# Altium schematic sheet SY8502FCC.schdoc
size 127 x 101 mm
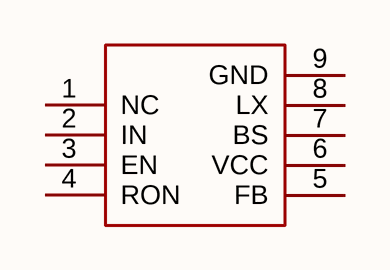
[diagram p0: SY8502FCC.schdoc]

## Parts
U?  sy8502fcc  [SOIC-8_L4.9-W3.9-P1.27-LS6.0-BL-EP]  (value not drawn)

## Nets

Not connected (* = marked no-connect by the designer): U? 1(NC) 2(IN) 3(EN) 4(RON) 5(FB) 6(VCC) 7(BS) 8(LX) 9(GND)

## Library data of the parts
U? = sy8502fcc: 功能类型:降压型;工作电压:7V~85V;输出电压:-;输出电流:1.2A;输出类型:可调;; Manufacturer: Silergy(矽力杰); AddInBom: yes; ModelId: 3febf2d495b54c0da7c8bb4287865e8b; ModelTransform: 192.913,236.22,0,0,0,0,0,0,0; Function: 降压型; Voltage - Supply: 7V~85V; Output Current: 1.2A; Frequency - Switching: 340kHz; Synchronous Rectifier: 是; Number of Outputs: 1; Topology: 降压式; Quiescent Current: 400uA; Switch tube (built-in/external): 内置; Output Type: 可调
